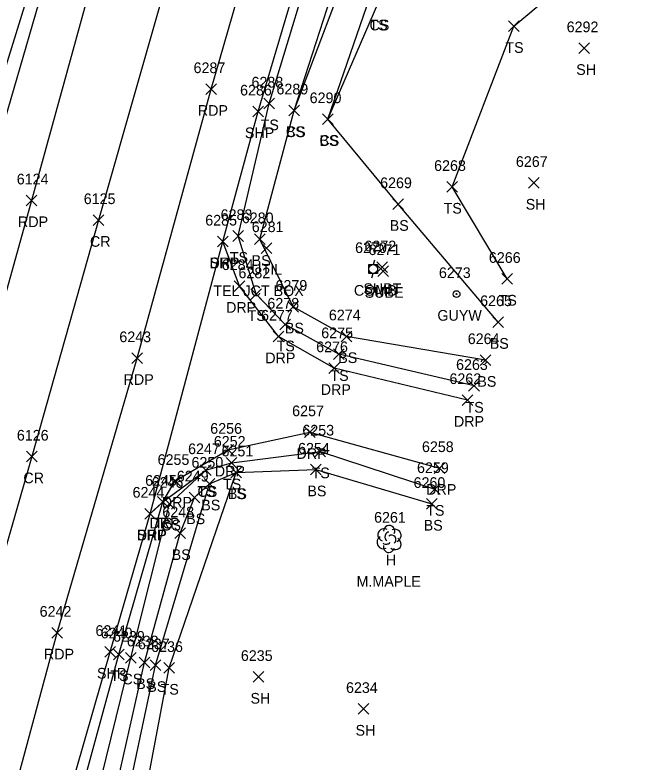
# Model space of a CAD drawing. Extents: x 1443912 to 1445411, y 621446 to 623693.
# Drawn here: x 1444480.1 to 1444596.2, y 621592 to 621732.1 of the extents above; entities that cross this region are included whole.
import ezdxf

# ---------------------------------------------------------------- set-up
doc = ezdxf.new("R2010")
doc.units = 0
for name, color, linetype in [('L_A', 7, 'Continuous'), ('L_C', 7, 'Continuous'), ('L_I', 7, 'Continuous'), ('L_TIC', 7, 'Continuous'), ('LELB', 7, 'Continuous'), ('LTD', 7, 'Continuous'), ('P_A', 7, 'Continuous'), ('P_I', 7, 'Continuous'), ('P_TIC', 7, 'Continuous'), ('PET', 7, 'Continuous'), ('PRC', 7, 'Continuous'), ('PSP', 7, 'Continuous'), ('R_A', 7, 'Continuous'), ('R_I', 7, 'Continuous'), ('R_TIC', 7, 'Continuous'), ('RDP', 7, 'Continuous'), ('U_A', 7, 'Continuous'), ('U_C', 7, 'Continuous'), ('U_I', 7, 'Continuous'), ('U_TIC', 7, 'Continuous'), ('UDEFAULT', 7, 'Continuous'), ('UP', 7, 'Continuous'), ('UPGW', 7, 'Continuous')]:
    doc.layers.add(name, color=color, linetype=linetype)

msp = doc.modelspace()

# ---------------------------------------------------------------- linework, layer by layer
at = {"layer": 'L_TIC'}
for points in [[(1444572.52, 621728.96), (1444574.52, 621730.96)], [(1444574.52, 621728.96), (1444572.52, 621730.96)], [(1444572.52, 621728.96), (1444574.52, 621730.96)], [(1444574.52, 621728.96), (1444572.52, 621730.96)], [(1444585.72, 621724.83), (1444587.72, 621726.83)], [(1444587.72, 621724.83), (1444585.72, 621726.83)], [(1444526.67, 621714.46), (1444528.67, 621716.46)], [(1444528.67, 621714.46), (1444526.67, 621716.46)], [(1444531.36, 621713.17), (1444533.36, 621715.17)], [(1444533.36, 621713.17), (1444531.36, 621715.17)], [(1444531.36, 621713.17), (1444533.36, 621715.17)], [(1444533.36, 621713.17), (1444531.36, 621715.17)], [(1444537.66, 621711.53), (1444539.66, 621713.53)], [(1444539.66, 621711.53), (1444537.66, 621713.53)], [(1444537.66, 621711.53), (1444539.66, 621713.53)], [(1444539.66, 621711.53), (1444537.66, 621713.53)], [(1444560.95, 621698.83), (1444562.95, 621700.83)], [(1444562.95, 621698.83), (1444560.95, 621700.83)], [(1444576.26, 621699.58), (1444578.26, 621701.58)], [(1444578.26, 621699.58), (1444576.26, 621701.58)], [(1444550.83, 621695.6), (1444552.83, 621697.6)], [(1444552.83, 621695.6), (1444550.83, 621697.6)], [(1444520.9, 621689.63), (1444522.9, 621691.63)], [(1444522.9, 621689.63), (1444520.9, 621691.63)], [(1444524.96, 621689.03), (1444526.96, 621691.03)], [(1444526.96, 621689.03), (1444524.96, 621691.03)], [(1444571.26, 621681.59), (1444573.26, 621683.59)], [(1444573.26, 621681.59), (1444571.26, 621683.59)], [(1444524.23, 621678.72), (1444526.23, 621680.72)], [(1444526.23, 621678.72), (1444524.23, 621680.72)], [(1444531.18, 621676.37), (1444533.18, 621678.37)], [(1444533.18, 621676.37), (1444531.18, 621678.37)], [(1444569.57, 621673.49), (1444571.57, 621675.49)], [(1444571.57, 621673.49), (1444569.57, 621675.49)], [(1444529.66, 621673.02), (1444531.66, 621675.02)], [(1444531.66, 621673.02), (1444529.66, 621675.02)], [(1444541.18, 621670.82), (1444543.18, 621672.82)], [(1444543.18, 621670.82), (1444541.18, 621672.82)], [(1444539.75, 621667.47), (1444541.75, 621669.47)], [(1444541.75, 621667.47), (1444539.75, 621669.47)], [(1444567.24, 621666.37), (1444569.24, 621668.37)], [(1444569.24, 621666.37), (1444567.24, 621668.37)], [(1444565.06, 621661.53), (1444567.06, 621663.53)], [(1444567.06, 621661.53), (1444565.06, 621663.53)], [(1444536.21, 621649.23), (1444538.21, 621651.23)], [(1444538.21, 621649.23), (1444536.21, 621651.23)], [(1444519.62, 621647.14), (1444521.62, 621649.14)], [(1444521.62, 621647.14), (1444519.62, 621649.14)], [(1444514.8, 621645.74), (1444516.8, 621647.74)], [(1444516.8, 621645.74), (1444514.8, 621647.74)], [(1444514.8, 621645.74), (1444516.8, 621647.74)], [(1444516.8, 621645.74), (1444514.8, 621647.74)], [(1444520.5, 621645.32), (1444522.5, 621647.32)], [(1444522.5, 621645.32), (1444520.5, 621647.32)], [(1444520.5, 621645.32), (1444522.5, 621647.32)], [(1444522.5, 621645.32), (1444520.5, 621647.32)], [(1444535.4, 621645.84), (1444537.4, 621647.84)], [(1444537.4, 621645.84), (1444535.4, 621647.84)], [(1444515.52, 621643.2), (1444517.52, 621645.2)], [(1444517.52, 621643.2), (1444515.52, 621645.2)], [(1444515.52, 621643.2), (1444517.52, 621645.2)], [(1444517.52, 621643.2), (1444515.52, 621645.2)], [(1444557.7, 621642.2), (1444559.7, 621644.2)], [(1444559.7, 621642.2), (1444557.7, 621644.2)], [(1444506.75, 621639.81), (1444508.75, 621641.81)], [(1444508.75, 621639.81), (1444506.75, 621641.81)], [(1444512.69, 621640.62), (1444514.69, 621642.62)], [(1444514.69, 621640.62), (1444512.69, 621642.62)], [(1444508.02, 621639.43), (1444510.02, 621641.43)], [(1444510.02, 621639.43), (1444508.02, 621641.43)], [(1444557.18, 621639.41), (1444559.18, 621641.41)], [(1444559.18, 621639.41), (1444557.18, 621641.41)], [(1444509.98, 621633.9), (1444511.98, 621635.9)], [(1444511.98, 621633.9), (1444509.98, 621635.9)], [(1444498.52, 621611.21), (1444500.52, 621613.21)], [(1444500.52, 621611.21), (1444498.52, 621613.21)], [(1444500.75, 621610.58), (1444502.75, 621612.58)], [(1444502.75, 621610.58), (1444500.75, 621612.58)], [(1444503.32, 621609.71), (1444505.32, 621611.71)], [(1444505.32, 621609.71), (1444503.32, 621611.71)], [(1444505.39, 621609.17), (1444507.39, 621611.17)], [(1444507.39, 621609.17), (1444505.39, 621611.17)], [(1444507.93, 621608.66), (1444509.93, 621610.66)], [(1444509.93, 621608.66), (1444507.93, 621610.66)], [(1444524.69, 621606.98), (1444526.69, 621608.98)], [(1444526.69, 621606.98), (1444524.69, 621608.98)], [(1444544.38, 621600.98), (1444546.38, 621602.98)], [(1444546.38, 621600.98), (1444544.38, 621602.98)]]:
    msp.add_lwpolyline(points, dxfattribs=at)
at = {"layer": 'LELB'}
for points in [[(1444574.55, 622074.53), (1444566.78, 622059.21), (1444562.93, 622059.13), (1444561.5, 622033.21), (1444553.8, 621993.71), (1444545.42, 621962.05), (1444531.89, 621911.31), (1444519.55, 621865.32), (1444501.88, 621802.99), (1444488.02, 621753.84), (1444471.78, 621701.48), (1444460.31, 621656.88), (1444459.55, 621655.45), (1444452.09, 621632.21), (1444445.68, 621624.35), (1444438.52, 621621.89)], [(1444566.06, 621662.53), (1444540.75, 621668.47), (1444530.66, 621674.02), (1444525.23, 621679.72), (1444521.9, 621690.63), (1444527.67, 621715.46), (1444537.6, 621748.27), (1444544.57, 621771.14), (1444552.88, 621800.55), (1444569.34, 621862.36), (1444584.53, 621915.31), (1444599.33, 621969.16), (1444603.57, 621978.29), (1444612.14, 621984.45), (1444630.38, 621984.58), (1444648.65, 621983.32), (1444669.84, 621978.95)], [(1444573.52, 621729.96), (1444606.82, 621757.8), (1444615.68, 621770.45), (1444599.05, 621772.87), (1444599.34, 621775.96), (1444583.66, 621779.46), (1444578.87, 621781.94), (1444577.18, 621792.61), (1444574.39, 621805.13), (1444589.72, 621856.09), (1444605.09, 621910.11), (1444615.08, 621952.69), (1444616.59, 621961.76), (1444617.15, 621962.73), (1444617.2, 621963.71), (1444617.35, 621964.73), (1444618.57, 621976.39)], [(1444532.36, 621714.17), (1444542.69, 621746.08), (1444548.67, 621769.62)], [(1444568.24, 621667.37), (1444542.18, 621671.82), (1444532.18, 621677.37), (1444525.96, 621690.03), (1444532.36, 621714.17), (1444544.31, 621745.69), (1444553.15, 621768.51), (1444555.18, 621767.73)], [(1444570.57, 621674.49), (1444551.83, 621696.6), (1444538.66, 621712.53), (1444549.59, 621744.28), (1444555.18, 621767.73)], [(1444538.66, 621712.53), (1444548.04, 621734.17), (1444561.21, 621741.33), (1444551.99, 621743.97), (1444573.49, 621760.96)], [(1444572.26, 621682.59), (1444561.95, 621699.83), (1444573.52, 621729.96)], [(1444458.38, 621461.67), (1444474.56, 621518.47), (1444487.36, 621567.59), (1444499.52, 621612.21), (1444507.75, 621640.81), (1444515.8, 621646.74), (1444520.62, 621648.14), (1444537.21, 621650.23), (1444558.7, 621643.2)], [(1444463.61, 621461.22), (1444481.31, 621515.95), (1444494.23, 621565.71), (1444504.32, 621610.71), (1444510.98, 621634.9), (1444513.69, 621641.62), (1444516.52, 621644.2), (1444521.5, 621646.32), (1444536.4, 621646.84), (1444558.18, 621640.41)], [(1444473.49, 621458.43), (1444486, 621514.41), (1444500.32, 621563.87), (1444508.93, 621609.66), (1444521.5, 621646.32)], [(1444481.31, 621515.95), (1444490.68, 621566.55), (1444501.75, 621611.58), (1444509.02, 621640.43), (1444515.8, 621646.74)], [(1444466.7, 621460.33), (1444483.84, 621514.87), (1444496.86, 621565.07), (1444506.39, 621610.17), (1444516.52, 621644.2)]]:
    msp.add_lwpolyline(points, dxfattribs=at)
at = {"layer": 'LTD'}
msp.add_line((1444550.12, 621633.89), (1444550.12, 621633.89), dxfattribs=at)
msp.add_line((1444550.12, 621633.89), (1444550.12, 621633.89), dxfattribs=at)
msp.add_arc((1444550.17, 621635.32), 1.05, 335.5272, 180.9563, dxfattribs=at)
for centre, major_axis, ratio, start_param, end_param in [((1444549.33, 621634.55), (1.21, -0.51), 0.895232, 1.570796, 4.712389), ((1444549.92, 621634.35), (-0.208, -0.792), 0.645439, 3.141593, 6.283185), ((1444550.62, 621633.72), (-0.5, 0.667), 0.989748, 3.141593, 6.283185), ((1444551.17, 621634.47), (-1.14, -0.48), 0.949671, 1.570796, 4.712389), ((1444549.04, 621633.18), (0.58, -1.04), 0.959034, 3.141593, 6.283185), ((1444549.67, 621633.14), (-0.625, -0.083), 0.423636, 0, 3.141593), ((1444551.12, 621633.05), (-1.09, 0.79), 0.841452, 1.570796, 4.712389), ((1444550.12, 621632.39), (0.26, 1.06), 0.942809, 1.570796, 4.712389)]:
    msp.add_ellipse(centre, major_axis=major_axis, ratio=ratio, start_param=start_param, end_param=end_param, dxfattribs=at)
at = {"layer": 'P_TIC'}
for points in [[(1444515.83, 621717.16), (1444517.83, 621719.16)], [(1444517.83, 621717.16), (1444515.83, 621719.16)], [(1444524.59, 621712.97), (1444526.59, 621714.97)], [(1444526.59, 621712.97), (1444524.59, 621714.97)], [(1444482.13, 621696.3), (1444484.13, 621698.3)], [(1444484.13, 621696.3), (1444482.13, 621698.3)], [(1444494.68, 621692.61), (1444496.68, 621694.61)], [(1444496.68, 621692.61), (1444494.68, 621694.61)], [(1444518.01, 621688.59), (1444520.01, 621690.59)], [(1444520.01, 621688.59), (1444518.01, 621690.59)], [(1444501.92, 621666.73), (1444503.92, 621668.73)], [(1444503.92, 621666.73), (1444501.92, 621668.73)], [(1444482.2, 621648.28), (1444484.2, 621650.28)], [(1444484.2, 621648.28), (1444482.2, 621650.28)], [(1444504.4, 621637.58), (1444506.4, 621639.58)], [(1444506.4, 621637.58), (1444504.4, 621639.58)], [(1444486.99, 621615.26), (1444488.99, 621617.26)], [(1444488.99, 621615.26), (1444486.99, 621617.26)], [(1444496.88, 621611.67), (1444498.88, 621613.67)], [(1444498.88, 621611.67), (1444496.88, 621613.67)]]:
    msp.add_lwpolyline(points, dxfattribs=at)
at = {"layer": 'PET'}
for points in [[(1444707.78, 622511.05), (1444700.03, 622482.58), (1444691.73, 622453.67), (1444679.73, 622411.23), (1444667.69, 622368.84), (1444653.08, 622317.67), (1444637.74, 622256.92), (1444626.42, 622209.58), (1444619.02, 622182.67), (1444605.37, 622130.08), (1444589.4, 622078.61), (1444578.44, 622026.86), (1444565.52, 621990.05), (1444556.87, 621958.17), (1444542.16, 621907.74), (1444529.8, 621863.07), (1444511.99, 621799.88), (1444498.16, 621751.76), (1444483.13, 621697.3), (1444470.84, 621653.16), (1444463.41, 621627.34), (1444449.07, 621575.52), (1444430.26, 621508.83), (1444421.17, 621471.46)], [(1444444.37, 621464.94), (1444461.94, 621522.87), (1444475.59, 621570.55), (1444487.99, 621616.26), (1444502.92, 621667.73), (1444516.83, 621718.16), (1444526.41, 621751.49), (1444537.28, 621789.32), (1444558.59, 621865), (1444573.59, 621917.93), (1444597.58, 621998.81), (1444610.14, 622044.19), (1444623.48, 622089.5), (1444632.2, 622118.09)]]:
    msp.add_lwpolyline(points, dxfattribs=at)
at = {"layer": 'PRC'}
msp.add_lwpolyline([(1444618.32, 622127.38), (1444604.97, 622075.74), (1444590.11, 622023.77), (1444578.57, 621985.29), (1444569.73, 621954.72), (1444555.25, 621903.96), (1444542.35, 621859.58), (1444524.46, 621796.02), (1444511.19, 621747.94), (1444495.68, 621693.61), (1444483.2, 621649.28), (1444475.93, 621623.97), (1444461.82, 621572.2), (1444443.22, 621505.41), (1444432.75, 621467.94)], dxfattribs=at)
at = {"layer": 'PSP'}
for points in [[(1444596.17, 622132.46), (1444585.6, 622096.58), (1444576.22, 622067.8), (1444567.15, 622029.85), (1444556.7, 621993.22), (1444548.18, 621960.88), (1444533.68, 621910.62), (1444520.92, 621865.12), (1444503.16, 621802.82), (1444490.06, 621753.65), (1444474.75, 621700.87), (1444461.97, 621656.27), (1444456.61, 621636.09), (1444438.52, 621570.3), (1444424.57, 621519.38), (1444411.29, 621473.11)], [(1444455.66, 621462.75), (1444472.05, 621519.48), (1444485.13, 621568.3), (1444497.88, 621612.67), (1444505.4, 621638.58), (1444519.01, 621689.59), (1444525.59, 621713.97), (1444535.94, 621748.74), (1444541.51, 621770.15), (1444550.94, 621803.78), (1444567.68, 621862.81), (1444582.56, 621915.85), (1444597.67, 621969.6), (1444608.45, 622008), (1444628.13, 622076.36), (1444639.3, 622115.36)]]:
    msp.add_lwpolyline(points, dxfattribs=at)
at = {"layer": 'R_TIC'}
for points in [[(1444518.01, 621688.59), (1444520.01, 621690.59)], [(1444520.01, 621688.59), (1444518.01, 621690.59)], [(1444521.11, 621680.25), (1444523.11, 621682.25)], [(1444523.11, 621680.25), (1444521.11, 621682.25)], [(1444528.46, 621670.77), (1444530.46, 621672.77)], [(1444530.46, 621670.77), (1444528.46, 621672.77)], [(1444538.85, 621664.85), (1444540.85, 621666.85)], [(1444540.85, 621664.85), (1444538.85, 621666.85)], [(1444563.82, 621658.88), (1444565.82, 621660.88)], [(1444565.82, 621658.88), (1444563.82, 621660.88)], [(1444534.3, 621652.85), (1444536.3, 621654.85)], [(1444536.3, 621652.85), (1444534.3, 621654.85)], [(1444519.01, 621649.56), (1444521.01, 621651.56)], [(1444521.01, 621649.56), (1444519.01, 621651.56)], [(1444558.62, 621646.13), (1444560.62, 621648.13)], [(1444560.62, 621646.13), (1444558.62, 621648.13)], [(1444509.08, 621643.72), (1444511.08, 621645.72)], [(1444511.08, 621643.72), (1444509.08, 621645.72)], [(1444506.75, 621639.81), (1444508.75, 621641.81)], [(1444508.75, 621639.81), (1444506.75, 621641.81)], [(1444504.4, 621637.58), (1444506.4, 621639.58)], [(1444506.4, 621637.58), (1444504.4, 621639.58)]]:
    msp.add_lwpolyline(points, dxfattribs=at)
at = {"layer": 'RDP'}
for points in [[(1444564.82, 621659.88), (1444539.85, 621665.85), (1444529.46, 621671.77), (1444522.11, 621681.25), (1444519.01, 621689.59)], [(1444505.4, 621638.58), (1444507.75, 621640.81), (1444510.08, 621644.72), (1444520.01, 621650.56), (1444535.3, 621653.85), (1444559.62, 621647.13)]]:
    msp.add_lwpolyline(points, dxfattribs=at)
at = {"layer": 'U_TIC'}
for points in [[(1444547.84, 621683.76), (1444549.84, 621685.76)], [(1444549.84, 621683.76), (1444547.84, 621685.76)], [(1444548.04, 621683.06), (1444550.04, 621685.06)], [(1444550.04, 621683.06), (1444548.04, 621685.06)]]:
    msp.add_lwpolyline(points, dxfattribs=at)
at = {"layer": 'UDEFAULT'}
for points in [[(1444526.16, 621687.36), (1444528.16, 621689.36)], [(1444528.16, 621687.36), (1444526.16, 621689.36)]]:
    msp.add_lwpolyline(points, dxfattribs=at)
at = {"layer": 'UP'}
for p, q in [((1444546.34, 621683.61), (1444546.34, 621685.27)), ((1444546.34, 621685.27), (1444548.01, 621685.27)), ((1444547.42, 621686.11), (1444547.17, 621685.27)), ((1444548.01, 621685.27), (1444548.01, 621683.61)), ((1444547.17, 621684.44), (1444547.17, 621684.44)), ((1444548.01, 621683.61), (1444546.34, 621683.61)), ((1444546.92, 621682.77), (1444547.17, 621683.61))]:
    msp.add_line(p, q, dxfattribs=at)
msp.add_circle((1444547.17, 621684.44), 0.833, dxfattribs=at)
at = {"layer": 'UPGW'}
for radius in [0.625, 0.0833]:
    msp.add_circle((1444562.8, 621679.75), radius, dxfattribs=at)

# ---------------------------------------------------------------- texts
at = {"layer": 'L_A'}
for s, p in [('TS', (1444546.45, 621729.17)), ('CS', (1444546.48, 621729.17)), ('TS', (1444571.93, 621724.96)), ('TS', (1444571.93, 621724.96)), ('SH', (1444585.21, 621720.83)), ('TS', (1444526.08, 621710.46)), ('CS', (1444530.8, 621709.17)), ('BS', (1444530.8, 621709.17)), ('CS', (1444537.1, 621707.53)), ('BS', (1444537.1, 621707.53)), ('TS', (1444560.36, 621694.83)), ('SH', (1444575.75, 621695.58)), ('BS', (1444550.27, 621691.6)), ('TS', (1444520.31, 621685.63)), ('BS', (1444524.4, 621685.03)), ('TS', (1444570.67, 621677.59)), ('TS', (1444523.64, 621674.72)), ('BS', (1444530.62, 621672.37)), ('TS', (1444529.07, 621669.02)), ('BS', (1444569.01, 621669.49)), ('BS', (1444540.62, 621666.82)), ('TS', (1444539.15, 621663.47)), ('BS', (1444566.68, 621662.37)), ('TS', (1444564.47, 621657.53)), ('TS', (1444535.62, 621645.23)), ('TS', (1444519.03, 621643.14)), ('TS', (1444514.21, 621641.74)), ('CS', (1444514.24, 621641.74)), ('TS', (1444519.91, 621641.32)), ('BS', (1444519.94, 621641.32)), ('BS', (1444534.84, 621641.84)), ('BS', (1444514.96, 621639.2)), ('BS', (1444514.96, 621639.2)), ('TS', (1444557.11, 621638.2)), ('TS', (1444506.16, 621635.81)), ('CS', (1444507.46, 621635.43)), ('BS', (1444512.13, 621636.62)), ('BS', (1444556.63, 621635.41)), ('BS', (1444509.42, 621629.9)), ('H', (1444549.56, 621628.89)), ('TS', (1444497.92, 621607.21)), ('CS', (1444500.19, 621606.58)), ('BS', (1444502.76, 621605.71)), ('BS', (1444504.84, 621605.17)), ('TS', (1444507.34, 621604.66)), ('SH', (1444524.18, 621602.98)), ('SH', (1444543.87, 621596.98))]:
    msp.add_text(s, height=2, dxfattribs=at).set_placement(p)
at = {"layer": 'L_C'}
msp.add_text('M.MAPLE', height=2, dxfattribs=at).set_placement((1444544.06, 621624.89))
at = {"layer": 'L_I'}
for s, p in [('6292', (1444583.42, 621728.83)), ('6288', (1444524.37, 621718.46)), ('6289', (1444529.05, 621717.17)), ('6289', (1444529.05, 621717.17)), ('6290', (1444535.27, 621715.53)), ('6290', (1444535.27, 621715.53)), ('6268', (1444558.59, 621702.83)), ('6267', (1444573.91, 621703.58)), ('6269', (1444548.47, 621699.6)), ('6283', (1444518.59, 621693.63)), ('6280', (1444522.56, 621693.03)), ('6266', (1444568.85, 621685.59)), ('6282', (1444521.93, 621682.72)), ('6279', (1444528.87, 621680.37)), ('6265', (1444567.21, 621677.49)), ('6278', (1444527.35, 621677.02)), ('6274', (1444538.87, 621674.82)), ('6275', (1444537.44, 621671.47)), ('6264', (1444564.89, 621670.37)), ('6263', (1444562.7, 621665.53)), ('6253', (1444533.9, 621653.23)), ('6252', (1444517.31, 621651.14)), ('6247', (1444512.49, 621649.74)), ('6247', (1444512.49, 621649.74)), ('6254', (1444533.09, 621649.84)), ('6251', (1444518.76, 621649.32)), ('6251', (1444518.76, 621649.32)), ('6250', (1444513.13, 621647.2)), ('6250', (1444513.13, 621647.2)), ('6259', (1444555.38, 621646.2)), ('6245', (1444504.45, 621643.81)), ('6249', (1444510.38, 621644.62)), ('6246', (1444505.66, 621643.43)), ('6260', (1444554.74, 621643.41)), ('6248', (1444507.67, 621637.9)), ('6261', (1444547.34, 621636.89)), ('6240', (1444496.12, 621615.21)), ('6239', (1444498.43, 621614.58)), ('6238', (1444501.01, 621613.71)), ('6237', (1444503.09, 621613.17)), ('6236', (1444505.57, 621612.66)), ('6235', (1444522.38, 621610.98)), ('6234', (1444542.08, 621604.98))]:
    msp.add_text(s, height=2, dxfattribs=at).set_placement(p)
at = {"layer": 'P_A'}
for s, p in [('RDP', (1444514.32, 621713.16)), ('SHP', (1444523.13, 621708.97)), ('RDP', (1444480.62, 621692.3)), ('CR', (1444494.11, 621688.61)), ('SHP', (1444516.55, 621684.59)), ('RDP', (1444500.41, 621662.73)), ('CR', (1444481.63, 621644.28)), ('SHP', (1444502.93, 621633.58)), ('RDP', (1444485.48, 621611.26)), ('SHP', (1444495.42, 621607.67))]:
    msp.add_text(s, height=2, dxfattribs=at).set_placement(p)
at = {"layer": 'P_I'}
for s, p in [('6287', (1444513.52, 621721.16)), ('6286', (1444522.23, 621716.97)), ('6124', (1444480.39, 621700.3)), ('6125', (1444492.94, 621696.61)), ('6285', (1444515.71, 621692.59)), ('6243', (1444499.61, 621670.73)), ('6126', (1444480.41, 621652.28)), ('6244', (1444502.09, 621641.58)), ('6242', (1444484.68, 621619.26)), ('6241', (1444495.14, 621615.67))]:
    msp.add_text(s, height=2, dxfattribs=at).set_placement(p)
at = {"layer": 'R_A'}
for p in [(1444516.5, 621684.59), (1444519.6, 621676.25), (1444526.95, 621666.77), (1444537.34, 621660.85), (1444562.3, 621654.88), (1444532.79, 621648.85), (1444517.49, 621645.56), (1444557.11, 621642.13), (1444507.57, 621639.72), (1444505.24, 621635.81), (1444502.88, 621633.58)]:
    msp.add_text('DRP', height=2, dxfattribs=at).set_placement(p)
at = {"layer": 'R_I'}
for s, p in [('6285', (1444515.71, 621692.59)), ('6284', (1444518.8, 621684.25)), ('6277', (1444526.16, 621674.77)), ('6276', (1444536.49, 621668.85)), ('6262', (1444561.46, 621662.88)), ('6257', (1444531.99, 621656.85)), ('6256', (1444516.64, 621653.56)), ('6258', (1444556.31, 621650.13)), ('6255', (1444506.78, 621647.72)), ('6245', (1444504.45, 621643.81)), ('6244', (1444502.09, 621641.58))]:
    msp.add_text(s, height=2, dxfattribs=at).set_placement(p)
at = {"layer": 'U_A'}
for s, p in [('UTIL', (1444524.32, 621683.36)), ('COMB', (1444543.56, 621679.44)), ('SUBT', (1444545.33, 621679.76)), ('SUBE', (1444545.58, 621679.06)), ('GUYW', (1444559.2, 621674.75))]:
    msp.add_text(s, height=2, dxfattribs=at).set_placement(p)
at = {"layer": 'U_C'}
msp.add_text('TEL JCT BOX', height=2, dxfattribs=at).set_placement((1444517.22, 621679.36))
at = {"layer": 'U_I'}
for s, p in [('6281', (1444524.42, 621691.36)), ('6270', (1444543.78, 621687.44)), ('6272', (1444545.53, 621687.76)), ('6271', (1444546.3, 621687.06)), ('6273', (1444559.49, 621682.75))]:
    msp.add_text(s, height=2, dxfattribs=at).set_placement(p)

doc.saveas('drawing.dxf')
